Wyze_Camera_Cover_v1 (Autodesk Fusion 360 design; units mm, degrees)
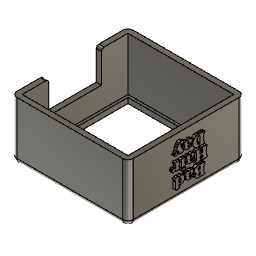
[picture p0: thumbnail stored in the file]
sketch "Sketch1" plane through (0, 0, 0) normal (0, 0, 1) x axis (1, 0, 0)
  line L1 (-27.94, 27.94) -> (27.94, 27.94)
  line L2 (-27.94, -27.94) -> (-27.94, 27.94)
  line L3 (27.94, -27.94) -> (-27.94, -27.94)
  line L4 (27.94, 27.94) -> (27.94, -27.94)
  line L5 (-27.94, -27.94) -> (27.94, 27.94)
  line L6 (27.94, -27.94) -> (-27.94, 27.94)
  point P6 (0, 0)
  point P1 (0, 0)
  point P2 (27.94, 27.94)
  point P5 (27.94, -27.94)
  horizontal L1
  perpendicular L1 L2
  parallel L1 L3
  parallel L2 L4
  coincident L5 P6
  coincident L6 P6
  coincident P1 P6
  dimension "d3" distance P2 P5 = 55.88
extrude "Extrude1" new body sketch "Sketch1" profile of L1 L2 L3 L4 along normal blind 27.94
shell "Shell1" innerThickness 2.54
fillet "Fillet1" radius 2.54
sketch "Sketch2" plane through (-27.94, 0, 0) normal (-1, 0, 0) x axis (0, -1, 0)
  line L1 (-25.4, 2.54) -> (-25.4, 27.94)
  line L2 (25.4, 2.54) -> (-25.4, 2.54)
  line L3 (25.4, 27.94) -> (25.4, 2.54)
  line L4 (-25.4, 27.94) -> (25.4, 27.94)
  line L5 (12.7, 27.94) -> (-12.7, 27.94)
  line L6 (12.7, 12.7) -> (12.7, 27.94)
  line L7 (-12.7, 12.7) -> (12.7, 12.7)
  line L8 (-12.7, 27.94) -> (-12.7, 12.7)
  line L9 (-25.4, 27.94) -> (-12.7, 27.94)
  point P6 (-12.7, 27.94)
  point P2 (-25.4, 27.94)
  point P10 (-25.4, 27.94)
  point P8 (12.7, 12.7)
  point P9 (-12.7, 12.7)
  point P7 (12.7, 27.94)
  horizontal L5
  vertical L6
  horizontal L7
  vertical L8
  coincident L4 P6
  coincident P2 P10
  dimension "d6" distance P8 P9 = 25.4
  dimension "d7" distance P6 P10 = 12.7
  dimension "d19" distance P7 P8 = 15.24
extrude "Extrude2" cut sketch "Sketch2" profile of L4 L5 L6 L7 L8 to an object
fillet "Fillet2" radius 1.27
sketch "Sketch3" plane through (27.94, 0, 0) normal (1, 0, 0) x axis (0, 1, 0)
  line L1 (25.4, 27.94) -> (25.4, 2.54)
  line L2 (-25.4, 27.94) -> (25.4, 27.94)
  line L3 (-25.4, 2.54) -> (-25.4, 27.94)
  line L4 (25.4, 2.54) -> (-25.4, 2.54)
  curve K1 (-6.7552, 10.8617) -> (7.8076, 10.8617)
  curve K2 (-6.7552, 3.2417) -> (-6.7552, 10.8617)
  curve K3 (7.8076, 3.2417) -> (-6.7552, 3.2417)
  curve K4 (7.8076, 10.8617) -> (7.8076, 3.2417)
  curve K5 (-8.0632, 17.4046) -> (9.0036, 17.4046)
  curve K6 (-8.0632, 9.7846) -> (-8.0632, 17.4046)
  curve K7 (9.0036, 9.7846) -> (-8.0632, 9.7846)
  curve K8 (9.0036, 17.4046) -> (9.0036, 9.7846)
  curve K9 (-7.0268, 25.0029) -> (7.8076, 25.0029)
  curve K10 (-7.0268, 17.3829) -> (-7.0268, 25.0029)
  curve K11 (7.8076, 17.3829) -> (-7.0268, 17.3829)
  curve K12 (7.8076, 25.0029) -> (7.8076, 17.3829)
  perpendicular K1 K2
  parallel K1 K3
  parallel K2 K4
  perpendicular K5 K6
  parallel K5 K7
  parallel K6 K8
  perpendicular K9 K10
  parallel K9 K11
  parallel K10 K12
emboss "Emboss1" sketch "Sketch3" Depth 1.27 Horizontal Distance 0 Vertical Distance 0 Rotation Angle 0
sketch "Sketch4" plane through (-27.94, 0, 0) normal (-1, 0, 0) x axis (0, -1, 0)
  line L1 (12.7, 12.7) -> (12.7, 26.67)
  line L2 (-12.7, 26.67) -> (-12.7, 12.7)
  line L3 (-25.4, 27.94) -> (-13.97, 27.94)
  line L4 (-25.4, 2.54) -> (-25.4, 27.94)
  line L5 (25.4, 2.54) -> (-25.4, 2.54)
  line L6 (25.4, 27.94) -> (25.4, 2.54)
  line L7 (13.97, 27.94) -> (25.4, 27.94)
  curve K1 (-22.4258, 10.5505) -> (22.3498, 10.5505)
  curve K2 (-22.4258, 4.2005) -> (-22.4258, 10.5505)
  curve K3 (22.3498, 4.2005) -> (-22.4258, 4.2005)
  curve K4 (22.3498, 10.5505) -> (22.3498, 4.2005)
  line L8 (-12.7, 12.7) -> (12.7, 12.7)
  arc A1 centre (13.97, 26.67) radius 1.27 clockwise from (12.7, 26.67) to (13.97, 27.94)
  arc A2 centre (-13.97, 26.67) radius 1.27 clockwise from (-13.97, 27.94) to (-12.7, 26.67)
  perpendicular K1 K2
  parallel K1 K3
  parallel K2 K4
emboss "Emboss2" sketch "Sketch4" Depth 1.27 Horizontal Distance 0 Vertical Distance 0 Rotation Angle 0
sketch "Sketch6" plane through (0, 0, 0) normal (0, 0, -1) x axis (1, 0, 0)
  line L1 (25.4, 25.4) -> (25.4, -25.4)
  line L2 (-25.4, 25.4) -> (25.4, 25.4)
  line L3 (-25.4, -25.4) -> (-25.4, 25.4)
  line L4 (25.4, -25.4) -> (-25.4, -25.4)
  line L5 (-24.13, -24.13) -> (24.13, -24.13)
  line L6 (-24.13, 24.13) -> (-24.13, -24.13)
  line L7 (24.13, 24.13) -> (-24.13, 24.13)
  line L8 (24.13, -24.13) -> (24.13, 24.13)
  line L9 (-24.13, 24.13) -> (24.13, -24.13)
  line L10 (24.13, 24.13) -> (-24.13, -24.13)
  point P10 (0, 0)
  point P1 (0, 0)
  point P8 (-24.13, 24.13)
  point P9 (24.13, 24.13)
  point P6 (24.13, -24.13)
  horizontal L5
  perpendicular L5 L6
  parallel L5 L7
  parallel L6 L8
  coincident L9 P10
  coincident L10 P10
  coincident P1 P10
  dimension "d20" distance P8 P9 = 48.26
  dimension "d21" distance P6 P9 = 48.26
extrude "Extrude3" cut sketch "Sketch6" profile of L5 L6 L7 L8 no distance stored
